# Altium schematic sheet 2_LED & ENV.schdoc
size 307 x 218 mm; Symbol: Drawing-Symbol_A4; Device: Drawing-Symbol_A4; @Project Name: Bed Temp Regulation; @Page Count: 4; @Update Date: 2026-02-17; @Create Date: 2026-02-16; @Schematic Name: Schematic Main; @Page No: 2; @Page Name: LED & ENV; Company: EasyEDA.com; Version: V1.0; Page Size: A4; @Create Time: 11:54:07; @Update Time: 15:39:47; Width: 1170; Height: 825; Region Start: 1; X Region Count: 6; Y Region Count: 4; Blade Width: 10; Title Block Position: 3; @Board Name: Main Board
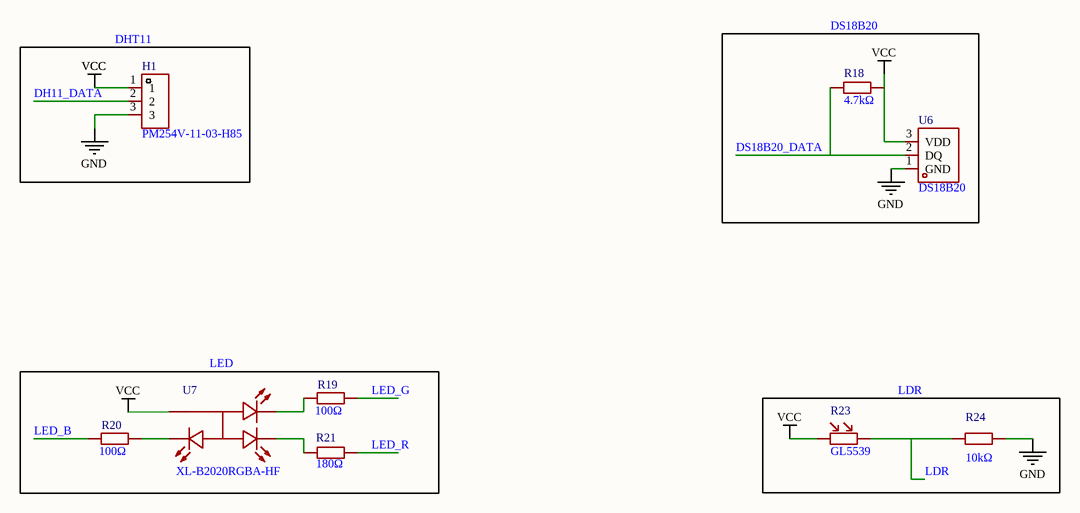
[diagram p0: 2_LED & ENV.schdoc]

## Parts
H1  PM254V-11-03-H85  [HDR-TH_3P-P2.54-V-F]
R18  4.7kΩ  [R0805]
R19  100Ω  [R0805]
R20  100Ω  [R0805]
R21  180Ω  [R0805]
R23  GL5539  [RES-TH_L5.1-W4.3-P3.40-D0.5]
R24  10kΩ  [R0805]
U6  DS18B20  [TO-92-3_L4.5-W3.5-P1.27-L]
U7  XL-B2020RGBA-HF  [LED-SMD_4P-L2.1-W2.1-P1.0-BL]

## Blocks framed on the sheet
DHT11: H1
DS18B20: R18 U6
LED: R19-R21 U7
LDR: R23 R24

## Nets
GND: H1.3 R24.2 U6.1(GND)
VCC: H1.1 R18.2 R23.1 U6.3(VDD) U7.3(A)
DH11_DATA: H1.2
DS18B20_DATA: R18.1 U6.2(DQ)
LDR: R23.2 R24.1
LED_B: R20.1
LED_G: R19.2
LED_R: R21.2
NetR19_1: R19.1 U7.4(C)
NetR20_2: R20.2 U7.2(C)
NetR21_1: R21.1 U7.1(C)

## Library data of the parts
H1 = PM254V-11-03-H85: Manufacturer: XFCN(兴飞); Add into BOM: yes; Holes Structure: 1x3P; Pitch: 2.54mm; Circular Hole / Square Hole: Square Hole; Number of Positions: 3P; Current Rating: 3A; Holes Direction: Top
R18 = 0805W8F4701T5E: Manufacturer: UNI-ROYAL(厚声); Add into BOM: yes; Tolerance: ±1%; Temperature Coefficient: ±100ppm/℃
R19 R20 = 0805W8F1000T5E_C17408: Manufacturer: UNI-ROYAL(厚声); Add into BOM: yes; Tolerance: ±1%; Temperature Coefficient: ±100ppm/℃
R21 = 0805W8F1800T5E: Manufacturer: UNI-ROYAL(厚声); Add into BOM: yes; Tolerance: ±1%; Power(Watts): 125mW; Voltage-Supply(Max): 150V; Temperature Coefficient: ±100ppm/℃
R23 = GL5539: Manufacturer: 森霸; Add into BOM: no; Convert to PCB: yes; Dark Resistance: 10MΩ; Cell Resistance @ Illuminance: 50kΩ~100kΩ; Voltage - Max: 150V; Wavelength - Peak: 540nm; Rise Time: 20ms; Fall Time: 30ms; γ Value: 0.8
R24 = 0805W8F1002T5E: Manufacturer: UNI-ROYAL(厚声); Add into BOM: yes; Tolerance: ±1%; Power(Watts): 125mW; Voltage-Supply(Max): 150V; Temperature Coefficient: ±100ppm/℃
U6 = DS18B20: Manufacturer: HXY MOSFET(华轩阳电子); Symbol: DS18B20_C5451632; Add into BOM: no; Convert to PCB: yes; Tolerance: ±0.4℃; Voltage - Supply: 2.5V~5.5V
U7 = XL-B2020RGBA-HF: Manufacturer: XINGLIGHT(成兴光); Add into BOM: yes; Diode Configuration: Common Anode; Wavelength - Dominant: B:460nm~470nm；G:520nm~530nm；R:620nm~630nm; Peak Wavelength: G:520nm；R:625nm；B:465nm; Luminous Intensity: G:240mcd~780mcd；R:55mcd~280mcd；B:75mcd~380mcd; Viewing Angle: 120°; Forward Current: R:20mA；B:20mA；G:20mA; Forward Voltage(Vf): G:2.6V~3.2V；R:1.9V~2.3V；B:2.6V~3.2V; Antistatic Capacity: B:2000V；R:2000V；G:2000V; Power(Watts): G:70mW；B:70mW；R:50mW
